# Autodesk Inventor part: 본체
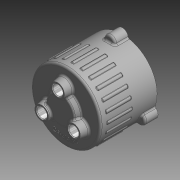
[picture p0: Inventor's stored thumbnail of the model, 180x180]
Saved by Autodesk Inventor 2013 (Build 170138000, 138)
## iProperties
Created: 2015-11
Part Number: 본체
Document SubType Name: 모델링
Designer: mdu
Material: 일반
Density: 1 g/cm^3
Mass: 250.598 g
Surface Area: 733.607 cm^2
Volume: 250.598 cm^3
변환 표준: STEP AP214IS
파일 이름: C:\Users\SeoGD\Desktop\?쒗뿕\紐몄껜.stp
전처리기: Build: 253, Release: 2010 SP1 - Date: Wed 07/29/2009
전송 단위: 밀리미터
불확실성: 0.01
Author: mdu
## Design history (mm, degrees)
sketch "스케치2"
  geometry: C1 r 52 at (0, 0); 1 further point
  constraints: 1 centre point, 1 coincident
  dimensions: "d9" = 104 diameter of C1
extrude "돌출2" new body sketch "스케치2" distance "d10" = 85.5; taper "d11" = 0 deg
feature "쉘1" dims "d12" = 7
sketch "스케치3" dims "d13" = 55
  geometry: C1 r 7.5 at (0, 27.5); C2 r 12.5 at (0, 27.5); 2 further points
  constraints: 2 centre point, 2 coincident, 2 vertical alignment, 2 other
  dimensions: "d14" = 15 diameter of C1; "d15" = 25 diameter of C2
extrude "돌출3" join sketch "스케치3" distance "d16" = 12; taper "d17" = -10 deg
sketch "스케치4"
  geometry: L1 (0, 0)-(0, 93.5); L2 (0, 71.5)-(12.624, 71.5); L3 (-45, 78.5)-(45, 78.5) reference; L4 (-52, 85.5)-(52, 85.5) reference; L5 (12.624, 71.5)-(14.5, 78.5); L6 (20.381, 93.5)-(0, 93.5); L7 (25, 85.5)-(14.5, 78.5); L8 (25, 85.5)-(20.381, 93.5)
  constraints: 12 end point, 3 point on line, 1 perpendicular, 1 vertical
  dimensions: "d35" = 105 deg angle of L5 L3; "d36" = 7 distance between parallel lines of L2 L3; "d37" = 8 distance between parallel lines of L6 L4; "d51" = 29 diameter of L5.end L1; "d92" = 50 diameter of L7.start L1; "d93" = 120 deg angle of L6 L8
revolve "회전1" sketch "스케치4" stored, may be unused: angle "d38" = 90 deg
hole "구멍2" diameter "d20" = 15; stored, may be unused: countersink angle "d24" = 90 deg, drill point angle "d26" = 118 deg; dims "d18" = 10, "d19" = 10, "d21" = 6, "d22" = 4, "d23" = 2, "d25" = 15
chamfer "모따기1" distance "d27" = 1; stored, may be unused: second distance "d28" = 2, angle "d29" = 45 deg
hole "구멍3" diameter "d41" = 15; stored, may be unused: countersink angle "d45" = 90 deg, drill point angle "d47" = 0 deg; dims "d42" = 6, "d43" = 22, "d44" = 13, "d46" = 16, "d96" = 10, "d97" = 10
chamfer "모따기2" distance "d48" = 1; stored, may be unused: second distance "d49" = 2, angle "d50" = 45 deg
fillet "모깎기1" dims "d52" = 3
fillet "모깎기2" dims "d53" = 3, "d72" = 0.2, "d94" = 2
sketch "스케치5"
  geometry: A1 r 52 centre (0, 0) between (52, 0) and (-8.472, 51.305) reference; A2 r 8.5 centre (0, 52) between (8.472, 51.305) and (-8.472, 51.305); 1 further point
  constraints: 5 point on circle, 1 centre point, 1 horizontal alignment
  dimensions: "d54" = 90 deg dimension on point (0, 0) A2.centre A1.start; "d55" = 52 distance of A2.centre point (0, 0); "d56" = 17 diameter of A2
extrude "돌출4" join sketch "스케치5" distance "d57" = 20; taper "d58" = 0 deg
fillet "모깎기3" dims "d59" = 3
hole "구멍4" diameter "d62" = 4.134; stored, may be unused: countersink angle "d66" = 90 deg, drill point angle "d68" = 118 deg; dims "d60" = 10, "d61" = 10, "d63" = 12, "d64" = 22, "d65" = 13, "d67" = 15
sketch "스케치6"
  geometry: C1 r 49 at (0, 0) reference; C2 r 42.5 at (0, 0); 1 further point
  constraints: 1 centre point, 1 coincident, 1 other
  dimensions: "d73" = 85 diameter of C2
feature "엠보싱1" sketch "스케치6" dims "d74" = 0.5, "d75" = 0
node "작업 평면1"
sketch "스케치7"
  geometry: A1 r 52 centre (0, 0) between (4.478, 51.807) and (-4.478, 51.807) reference; A2 r 3 centre (0, 50) between (2.28, 51.95) and (-2.28, 51.95); 1 further point
  constraints: 4 point on circle, 1 centre point, 1 vertical alignment
  dimensions: "d77" = 3 radius of A2; "d91" = 50 distance of point (0, 0) A2.centre
extrude "돌출5" join sketch "스케치7" distance "d79" = 38; taper "d80" = 0 deg
fillet "모깎기4" dims "d81" = 1
fillet "모깎기5" dims "d82" = 1
node "솔리드1"
node "솔리드 본체"
node "곡면 본체"
pattern_circular "원형 패턴1" dims "d31" = 360 deg
pattern_circular "원형 패턴2" dims "d70" = 360 deg
pattern_circular "원형 패턴3" dims "d84" = 360 deg
node "솔리드2"
